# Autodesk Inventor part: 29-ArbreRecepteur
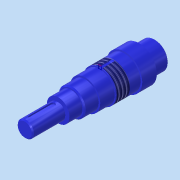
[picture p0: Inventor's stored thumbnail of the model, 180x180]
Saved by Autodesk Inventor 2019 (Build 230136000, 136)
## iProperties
Created: 2023-04
Part Number: 29-ArbreRecepteur
Material: Générique
Document SubType Name: Modeling
Designer: Thier
Density: 1 g/cm^3
Appearance: Bleu - Peinture murale - Brillant
Author: Thier
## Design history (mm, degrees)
revolve "Révolution1" stored, may be unused: angle "d14" = 90 deg
feature "Filetage2" dims "d35" = 12, "d36" = 10
chamfer "Chanfrein3" distance "d44" = 1; stored, may be unused: second distance "d45" = 2, angle "d46" = 45 deg
chamfer "Chanfrein4" distance "d47" = 1; stored, may be unused: second distance "d48" = 2, angle "d49" = 45 deg
node "Plan de construction2"
sketch "Esquisse4"
  geometry: L1 (-2, 9.683)-(2, 9.683); L2 (2, 9.683)-(2, 6); L3 (2, 6)-(-2, 6); L4 (-2, 6)-(-2, 9.683); C1 r 7.5 at (0, 0) reference; 1 further point
  constraints: 8 end point, 2 parallel, 1 horizontal, 1 perpendicular
  dimensions: "d51" = 2 distance from line of C1.centre L2; "d52" = 4 distance of L1.start L1.end (= 2 x d51); "d53" = 6 distance from line of C1.centre L3
extrude "Extrusion3" cut sketch "Esquisse4" distance "d54" = 24; taper "d55" = 0 deg
fillet "Congé3" dims "d56" = 2
sketch "Esquisse7"
  geometry: L1 (-1.5, 17.143)-(1.5, 17.143); L2 (1.5, 17.143)-(1.5, 14); L3 (1.5, 14)-(-1.5, 14); L4 (-1.5, 14)-(-1.5, 17.143); C1 r 12.5 at (0, 0) reference; C2 r 11.5 at (0, 0) reference; 1 further point
  constraints: 8 end point, 2 parallel, 1 horizontal, 1 perpendicular
  dimensions: "d60" = 1.5 distance from line of C1.centre L2; "d61" = 3 distance of L1.start L1.end (= 2 x d60); "d62" = 14 distance from line of C2.centre L3
extrude "Extrusion4" cut sketch "Esquisse7" distance "d63" = 14; taper "d64" = 0 deg; dims "d65" = 12.5, "d66" = 0
fillet "Congé4" dims "d67" = 5
node "Solide1"
sketch "Esquisse1"
  geometry: L1 (0, 0)-(7.5, 0); L2 (7.5, 0)-(7.5, -30); L3 (7.5, -30)-(6.5, -30); L4 (6.5, -30)-(6.5, -31); L5 (6.5, -31)-(10.5, -31); L6 (12.5, -43)-(12.5, -56); L7 (12.5, -56)-(14, -56); L8 (15, -69.5)-(15, -92.5); L9 (15, -92.5)-(16.5, -92.5); L10 (16.5, -92.5)-(16.5, -106); L11 (16.5, -106)-(14, -106); L12 (14, -106)-(14, -108); L13 (14, -108)-(12.5, -108); L14 (12.5, -108)-(12.5, -121); L15 (12.5, -121)-(0, -121); L16 (0, -121)-(0, 0); L17 (14, -69.5)-(14, -56); L18 (15, -69.5)-(14, -69.5); L19 (12.5, -43)-(-5.123, -43); L20 (10.5, -31)-(10.5, -43)
  constraints: 40 end point, 12 perpendicular, 3 horizontal, 3 parallel, 2 vertical, 1 point on line
  dimensions: "d0" = 33 diameter of L10 L16; "d1" = 28 diameter of L12 L16; "d2" = 25 diameter of L14 L16; "d3" = 30 diameter of L8 L16; "d4" = 25 diameter of L6 L16; "d5" = 13 diameter of L4 L16; "d6" = 15 diameter of L2 L16; "d7" = 30 distance of L1.end L2.end; "d8" = 1 distance of L3.end L4.end; "d11" = 13.5 distance of L9.end L10.end; "d12" = 2 distance of L11.end L12.end; "d13" = 13 distance of L13.end L14.end; "d33" = 23 distance of L8.start L8.end; "d34" = 28 diameter of L17 L16; "d40" = 13 distance between parallel lines of L7 L19; "d41" = 21 diameter of L20 L16; "d42" = 25 distance between parallel lines of L7 L5; "d43" = 36.5 distance between parallel lines of L9 L7; "d69" = 78 distance between parallel lines of L15 L19 (derived); "d70" = 49.5 distance from line of L9.end L19 (derived)
other parameters: "d50" = -4
